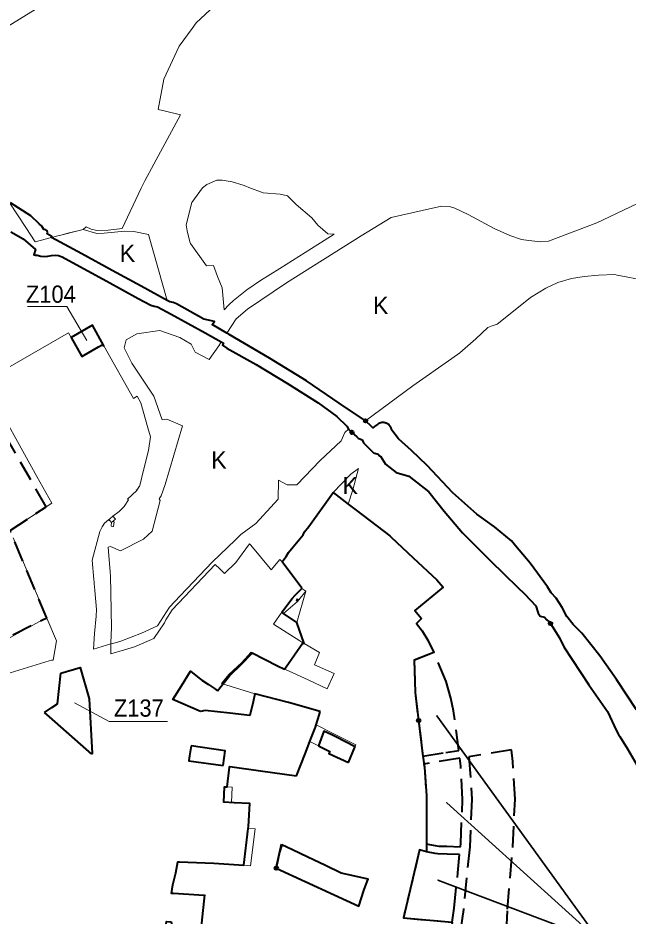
# Model space of a CAD drawing. Extents: x -650276 to -642489, y -1074425 to -1066658.
# Drawn here: x -646064 to -645214, y -1069855 to -1068604 of the extents above; entities that cross this region are included whole.
import ezdxf

# ---------------------------------------------------------------- set-up
doc = ezdxf.new("R2010")
doc.units = 0
doc.header["$LTSCALE"] = 9.6
doc.header["$PDMODE"] = 32
doc.header["$PDSIZE"] = 4.8
doc.linetypes.add('MEDIUM_DASHED', pattern=[4.5, 3, -1.5])
for name, color, linetype, lineweight in [('1', 7, 'Continuous', 13), ('4', 7, 'Continuous', 40), ('43', 7, 'Continuous', 13), ('44', 7, 'Continuous', 40), ('45', 7, 'Continuous', 40), ('46', 7, 'Continuous', 13), ('47', 7, 'Continuous', 13), ('61', 7, 'MEDIUM_DASHED', 40), ('62', 7, 'Continuous', 35)]:
    doc.layers.add(name, color=color, linetype=linetype, lineweight=lineweight)

msp = doc.modelspace()

# ---------------------------------------------------------------- hatches: boundary and pattern name
at = {"layer": '1'}
msp.add_hatch(color=256, dxfattribs=at).paths.add_polyline_path([(-645674.85, -1069417.32), (-645673.11, -1069414.76), (-645675.17, -1069413.36), (-645676.9, -1069415.91)])

# ---------------------------------------------------------------- linework, layer by layer
for p, q in [((-645673.11, -1069414.76), (-645663.41, -1069402.83)), ((-645694.21, -1069433.78), (-645674.85, -1069417.32))]:
    msp.add_line(p, q, dxfattribs=at)
for points in [[(-645954.63, -1068900.16), (-645938.5, -1068899.61), (-645919.15, -1068897.29), (-645892.53, -1068841.03), (-645887.72, -1068830.87), (-645875.187, -1068807.797), (-645837.77, -1068738.91), (-645858.824, -1068734.053), (-645868.98, -1068731.71), (-645860.91, -1068689.17), (-645839.55, -1068643.47), (-645821.454, -1068618.506), (-645816.02, -1068611.01), (-645751.23, -1068549.94)], [(-646028.19, -1068584.65), (-646136.66, -1068651.17), (-646149.99, -1068658.12), (-646149.04, -1068659.6), (-646152.41, -1068662.01), (-646157.02, -1068665.31), (-646115.89, -1068732.3), (-646110.72, -1068746.41), (-646100.168, -1068766.374), (-646094.58, -1068779.42), (-646089.04, -1068787.68), (-646088.06, -1068789.6), (-646105.32, -1068795.84), (-646115.95, -1068799.69), (-646109.35, -1068810.23), (-646081.72, -1068852.51), (-646075.56, -1068861.95), (-646053.3, -1068896.01)], [(-645766.07, -1068832.57), (-645779.72, -1068830.06), (-645787.33, -1068829.85), (-645801.24, -1068836.04), (-645807.42, -1068840.55), (-645822.26, -1068861.1), (-645829.76, -1068892.24), (-645828.71, -1068900.71), (-645825.84, -1068912.22), (-645824.55, -1068917.37), (-645823.83, -1068918.35), (-645801.57, -1068949.19), (-645791.76, -1068948.85), (-645786.17, -1068964.41), (-645779.83, -1068979.98), (-645777.16, -1069010.72)], [(-645777.16, -1069010.72), (-645770.47, -1069003.97), (-645764.17, -1068997.62), (-645745.65, -1068982.8), (-645726.46, -1068970.04), (-645699.5, -1068953.13), (-645637.82, -1068914.25), (-645623.92, -1068905.45), (-645632.76, -1068904.96), (-645646.49, -1068892.56), (-645655, -1068882.59), (-645676.5, -1068864.08), (-645688.54, -1068852.06), (-645699.05, -1068849.57), (-645722.69, -1068847.93), (-645742.6, -1068840.05), (-645746.62, -1068838.62), (-645750.71, -1068837.16), (-645766.07, -1068832.57)], [(-646053.3, -1068896.01), (-646040.33, -1068915.86), (-646017.55, -1068909.75), (-646010.48, -1068907.86), (-646004.88, -1068906.5), (-645980.93, -1068900.85), (-645973.36, -1068898.93), (-645969.47, -1068895.19), (-645962.49, -1068898.49), (-645954.63, -1068900.16)], [(-645739.3, -1069487.81), (-645702.82, -1069506.64), (-645659.84, -1069526.46), (-645633.29, -1069538.7), (-645623.545, -1069517.563), (-645651.26, -1069505.47), (-645644.18, -1069488.17), (-645665.58, -1069475.61), (-645667.31, -1069474.6), (-645671.75, -1069471.99), (-645708.48, -1069448.63), (-645696.45, -1069432.21), (-645682.28, -1069412.88), (-645678.06, -1069408.54), (-645668.61, -1069398.9), (-645696.19, -1069362.01), (-645699.25, -1069358.42), (-645711.75, -1069372.87), (-645713.14, -1069371.2), (-645740.01, -1069338.86), (-645741.7, -1069337.03), (-645760.59, -1069362.92), (-645776.73, -1069378.22), (-645783.23, -1069371.55), (-645789.7, -1069365.42), (-645849.68, -1069428.67), (-645858.11, -1069442.69), (-645860.14, -1069446.69), (-645875.02, -1069468.52), (-645902.19, -1069480.13), (-645916.13, -1069484.55), (-645934.97, -1069490.31), (-645935, -1069485.04), (-645935.03, -1069480.02), (-645935.05, -1069476.32), (-645959.32, -1069483.43), (-645957.52, -1069461.75), (-645955.52, -1069437.7), (-645954.74, -1069428.36), (-645957.17, -1069401.86), (-645957.69, -1069396.19), (-645958.02, -1069392.6), (-645958.23, -1069390.23), (-645958.59, -1069386.32), (-645961.03, -1069359.69), (-645950.49, -1069319.46), (-645947.21, -1069313.26), (-645943.67, -1069307.84), (-645938.32, -1069303.37), (-645936.46, -1069301.94), (-645932.07, -1069298.43), (-645923.56, -1069291.6), (-645916.39, -1069284.67), (-645910.4, -1069275.66), (-645911.64, -1069274.48), (-645898.96, -1069262.45), (-645899.61, -1069262.14), (-645899.34, -1069261.66), (-645898.67, -1069262.02), (-645895.95, -1069257.98), (-645895.9, -1069256.91), (-645895.36, -1069256.81), (-645895.25, -1069257.41), (-645888.98, -1069232.44), (-645882.56, -1069206.54), (-645879.84, -1069187.64), (-645883.39, -1069175.24), (-645893.36, -1069140.52), (-645898.3, -1069130.96), (-645903.35, -1069134.27), (-645944.69, -1069060.7), (-645946.84, -1069059.58), (-645952.21, -1069062.4), (-645975.48, -1069075.71), (-645990.13, -1069049.3), (-645993.85, -1069042.59), (-646106.31, -1069107.25)], [(-646107, -1069119.41), (-646037.99, -1069242.88), (-646017.15, -1069280.19), (-646075.49, -1069318.19)], [(-645928.65, -1069302.49), (-645932.07, -1069298.43), (-645936.46, -1069301.94), (-645938.32, -1069303.37)], [(-645938.32, -1069303.37), (-645935.71, -1069304.85), (-645934.38, -1069306.59)], [(-645934.38, -1069306.59), (-645934.21, -1069306.82), (-645934.66, -1069312.34), (-645934.17, -1069312.41), (-645931.98, -1069312.69), (-645931.24, -1069312.79), (-645930.48, -1069306.22), (-645931.2, -1069306.14), (-645931.07, -1069305.08), (-645933.12, -1069305.94), (-645928.65, -1069302.49)], [(-646071.21, -1069328.33), (-646023.96, -1069440.34), (-646010.65, -1069471.91), (-646015.16, -1069498.74), (-646017.63, -1069499.08), (-646020.75, -1069500), (-646075.48, -1069516.38)], [(-645668.61, -1069398.9), (-645678.06, -1069408.54), (-645682.28, -1069412.88), (-645696.45, -1069432.21), (-645694.21, -1069433.78)], [(-645676.9, -1069415.91), (-645675.17, -1069413.36), (-645673.11, -1069414.76), (-645663.41, -1069402.83), (-645668.61, -1069398.9)], [(-645694.21, -1069433.78), (-645674.85, -1069417.32), (-645676.9, -1069415.91)], [(-645696.45, -1069432.21), (-645708.48, -1069448.63), (-645671.75, -1069471.99)], [(-645665.58, -1069475.61), (-645675.91, -1069446.56), (-645694.21, -1069433.78), (-645696.45, -1069432.21)], [(-645671.75, -1069471.99), (-645667.31, -1069474.6), (-645665.58, -1069475.61)], [(-645808.28, -1069865.39), (-645806.07, -1069844.09), (-645804.38, -1069830.61), (-645804.28, -1069826.76), (-645812.18, -1069826.3), (-645847.62, -1069824.26), (-645850.63, -1069824.09), (-645848.35, -1069812.09), (-645844.57, -1069795.07), (-645841.41, -1069779.76), (-645791.2, -1069781.92), (-645749.48, -1069784.61), (-645740.394, -1069785.402), (-645733.972, -1069734.1), (-645743.36, -1069733.7), (-645743.01, -1069730.72), (-645741.43, -1069698.68), (-645766.701, -1069697.419), (-645766.017, -1069675.979), (-645773.02, -1069675.47), (-645769.36, -1069648), (-645769.298, -1069647.215), (-645726.57, -1069653.22), (-645676.34, -1069660.28), (-645670.23, -1069644.67), (-645664.19, -1069629.24), (-645657.52, -1069612.2), (-645629.78, -1069626.03), (-645630.93, -1069628.84), (-645603.7, -1069641.75), (-645594.58, -1069619.56), (-645593.609, -1069617.075), (-645625.81, -1069600.63), (-645648.68, -1069589.06), (-645644.56, -1069575.61), (-645643.16, -1069570.6), (-645734.5, -1069545.89), (-645780.85, -1069531.55), (-645770.66, -1069519.07), (-645753.05, -1069502.47), (-645739.3, -1069487.81)]]:
    msp.add_lwpolyline(points, dxfattribs=at)
for points in [[(-645675.91, -1069446.56), (-645663.41, -1069402.83), (-645673.11, -1069414.76), (-645674.85, -1069417.32), (-645694.21, -1069433.78)], [(-645674.85, -1069417.32), (-645673.11, -1069414.76), (-645675.17, -1069413.36), (-645676.9, -1069415.91)], [(-645647.25, -1069815.13), (-645623.75, -1069825.97), (-645589.23, -1069841.89), (-645582.31, -1069820.05), (-645577.52, -1069807.26), (-645576.34, -1069804.13), (-645613.84, -1069795.78), (-645635.79, -1069785.23), (-645660.57, -1069773.31), (-645681.76, -1069763.13), (-645698.16, -1069755.25), (-645705.3, -1069788.35)]]:
    msp.add_lwpolyline(points, close=True, dxfattribs=at)
at = {"layer": '4'}
for points in [[(-646027.49, -1069571.79), (-646017.39, -1069564.94), (-646009.52, -1069559.6), (-646004.7, -1069517.16)], [(-646004.7, -1069517.16), (-645977.73, -1069509.11), (-645965.36, -1069552.99), (-645960.78, -1069628.91), (-645961.36, -1069630.05)], [(-645961.36, -1069630.05), (-646020.4, -1069578.04), (-646027.49, -1069571.79)]]:
    msp.add_lwpolyline(points, dxfattribs=at)
at = {"layer": '4', "lineweight": 13}
msp.add_lwpolyline([(-645856.191, -1069584.407), (-645937.111, -1069584.407), (-645985.786, -1069558.403)], dxfattribs=at)
at = {"layer": '44'}
for points in [[(-645579.94, -1069165.52), (-645616.63, -1069140.8), (-645662.44, -1069109.89), (-645713.61, -1069078.06), (-645770.04, -1069045.34), (-645773.38, -1069043.46), (-645793.638, -1069031.021), (-645790.53, -1069027.19), (-645805.16, -1069023.52), (-645843.56, -1069002.41), (-645848.18, -1069000.48), (-645852.91, -1068999.62), (-645856.26, -1068997.79), (-645892.77, -1068977.86), (-645933.28, -1068955.74), (-645975.31, -1068932.8), (-646017.55, -1068909.75), (-646017.39, -1068908.42), (-646023.56, -1068905.05), (-646023.13, -1068903.12), (-646023.92, -1068900.73), (-646025.57, -1068899.39), (-646028.18, -1068898.89), (-646031.31, -1068894.32), (-646034.65, -1068891.12), (-646046.48, -1068879.92), (-646074.78, -1068861.51)], [(-646074.51, -1068901.9), (-646057.13, -1068911.62), (-646039.84, -1068926.67), (-646042.5, -1068933.91), (-646040.65, -1068934.59), (-646037.5, -1068934.7), (-646032.61, -1068936.1)], [(-646032.61, -1068936.1), (-646027.69, -1068936.6), (-646022.77, -1068936.12), (-646017.6, -1068934.89), (-646012.64, -1068934.34), (-646007.7, -1068935.18), (-646002.95, -1068936.95), (-645993.5, -1068942.1), (-645940.77, -1068970.74), (-645896.91, -1068994.75), (-645879.17, -1069004.02), (-645874.49, -1069005.73), (-645869.83, -1069006.45), (-645850.79, -1069016.84), (-645803.29, -1069042.92), (-645781.12, -1069055.29), (-645777.73, -1069057.2), (-645779.49, -1069059.92), (-645773.29, -1069063.99), (-645732.65, -1069086.82), (-645688.87, -1069113.44), (-645646.08, -1069140.37), (-645620.2, -1069159.26), (-645606.11, -1069172.98), (-645603.91, -1069176.86), (-645599, -1069181.48)], [(-645571.9, -1069173.43), (-645579.94, -1069165.52), (-645579.94, -1069165.52)], [(-645543.43, -1069178.39), (-645543.547, -1069177.727), (-645543.706, -1069177.053), (-645543.907, -1069176.37), (-645544.154, -1069175.682), (-645544.448, -1069174.993), (-645544.792, -1069174.308), (-645545.186, -1069173.63), (-645545.631, -1069172.966), (-645546.127, -1069172.32), (-645546.674, -1069171.699), (-645547.269, -1069171.107), (-645547.91, -1069170.551), (-645548.594, -1069170.034), (-645549.317, -1069169.563), (-645550.076, -1069169.141), (-645550.863, -1069168.772), (-645551.674, -1069168.459), (-645552.504, -1069168.203), (-645553.344, -1069168.007), (-645554.191, -1069167.87), (-645555.036, -1069167.793), (-645555.875, -1069167.772), (-645556.702, -1069167.808), (-645557.511, -1069167.896), (-645558.298, -1069168.035), (-645559.06, -1069168.219), (-645559.793, -1069168.445), (-645560.494, -1069168.709), (-645561.162, -1069169.007), (-645561.794, -1069169.334), (-645562.39, -1069169.686), (-645562.95, -1069170.06), (-645567.5, -1069173.46), (-645569.81, -1069175.03), (-645571.9, -1069173.43)], [(-645202.56, -1069568.23), (-645230.1, -1069525.98), (-645253.4, -1069493.06), (-645278.31, -1069461.33), (-645281.4, -1069458.4), (-645290.5, -1069449.03), (-645299.61, -1069437.97), (-645306.16, -1069425.55), (-645314.14, -1069412.54), (-645321.1, -1069405.21), (-645326.59, -1069396.64), (-645350.63, -1069363.98), (-645371.12, -1069339.47), (-645376.38, -1069332.65), (-645400.07, -1069313.32), (-645424.8, -1069295.24), (-645458.45, -1069265.56), (-645494.13, -1069227.63), (-645515.89, -1069206.66), (-645534.25, -1069190.56), (-645543.43, -1069178.39)], [(-645599, -1069181.48), (-645599, -1069181.48), (-645592.24, -1069187.73), (-645590.41, -1069189.45), (-645584.73, -1069191.88), (-645582.63, -1069195.88), (-645575.58, -1069203.57), (-645568.9, -1069209.87), (-645567.07, -1069210.45), (-645562.17, -1069212.02), (-645560.72, -1069214.25), (-645559.33, -1069214.54), (-645552.2, -1069225.59), (-645537.44, -1069237.41), (-645519.59, -1069242.38), (-645491.63, -1069264.25), (-645470.44, -1069291.24), (-645444.62, -1069321.35), (-645405.7, -1069360.27), (-645368.13, -1069397.37), (-645358.04, -1069406.84), (-645342.49, -1069423.06), (-645339.31, -1069433.27), (-645336.66, -1069437.47), (-645330.57, -1069438.89), (-645327.2, -1069442.53), (-645323.36, -1069445.79), (-645322.13, -1069447.96)], [(-645322.13, -1069447.96), (-645309.62, -1069467.79), (-645303.57, -1069480.49), (-645268.57, -1069533.23), (-645242.75, -1069570.26), (-645230.42, -1069597.39), (-645227.27, -1069602.68), (-645225.7, -1069605.32), (-645214.76, -1069622.37), (-645198.41, -1069650.49)]]:
    msp.add_lwpolyline(points, dxfattribs=at)
for p in [(-645579.94, -1069165.52), (-645599, -1069181.48), (-645322.13, -1069447.96)]:
    msp.add_point(p, dxfattribs=at)
at = {"layer": '45'}
msp.add_line((-645704.355, -1069788.786), (-645623.75, -1069825.97), dxfattribs=at)
for points in [[(-645944.69, -1069060.7), (-645960.67, -1069032.26), (-645990.13, -1069049.3), (-645975.48, -1069075.71), (-645952.21, -1069062.4)], [(-645944.69, -1069060.7), (-645960.67, -1069032.26), (-645990.13, -1069049.3), (-645975.48, -1069075.71), (-645952.21, -1069062.4)], [(-645952.21, -1069062.4), (-645946.84, -1069059.58), (-645944.69, -1069060.7)], [(-645952.21, -1069062.4), (-645946.84, -1069059.58), (-645944.69, -1069060.7)], [(-645668.722, -1069398.75), (-645696.19, -1069362.01), (-645692.38, -1069356.67), (-645690.81, -1069354.28), (-645687.22, -1069349), (-645680.8, -1069341.08), (-645667, -1069324.06), (-645664.89, -1069320.2), (-645658.9, -1069312.83), (-645625.11, -1069265.42), (-645604.114, -1069281.49), (-645594.94, -1069288.511)], [(-645594.94, -1069288.511), (-645583.13, -1069297.55), (-645546.19, -1069325.81), (-645544.26, -1069327.35), (-645513.41, -1069356.18), (-645480.72, -1069386.96), (-645471.738, -1069397.026), (-645511.464, -1069429.794), (-645501.878, -1069440.838)], [(-645675.91, -1069446.56), (-645694.21, -1069433.78), (-645696.45, -1069432.21), (-645682.28, -1069412.88), (-645678.06, -1069408.54), (-645668.61, -1069398.9), (-645668.722, -1069398.75)], [(-645501.878, -1069440.838), (-645508.994, -1069447.955), (-645501, -1069458), (-645493, -1069471), (-645484.783, -1069488.256), (-645512, -1069499), (-645511, -1069544), (-645506, -1069583)], [(-645786.388, -1069541.673), (-645779.376, -1069532.962), (-645778.754, -1069532.198), (-645769.369, -1069520.672), (-645768.995, -1069520.305), (-645752.715, -1069504.328), (-645738.986, -1069489.868), (-645737.897, -1069488.534), (-645702.82, -1069506.64), (-645692.87, -1069511.229), (-645690.84, -1069508.32), (-645667.31, -1069474.6), (-645665.58, -1069475.61), (-645675.91, -1069446.56)], [(-645836.44, -1069534.5), (-645824.05, -1069514.34), (-645811.75, -1069523.81), (-645808.1, -1069526.61), (-645799.07, -1069532.8), (-645790.62, -1069538.59), (-645786.388, -1069541.673)], [(-645810.08, -1069570.39), (-645848.78, -1069553.91), (-645836.44, -1069534.5)], [(-645643.16, -1069570.6), (-645687.29, -1069558.04), (-645734.5, -1069545.89), (-645736.8, -1069556.91), (-645741.14, -1069576.19), (-645769.04, -1069573), (-645803.513, -1069569.263), (-645810.08, -1069570.39)], [(-645676.34, -1069660.28), (-645670.23, -1069644.67), (-645664.19, -1069629.24), (-645657.52, -1069612.2), (-645656.15, -1069608.71), (-645649.91, -1069592.39), (-645648.68, -1069589.06), (-645644.56, -1069575.61), (-645643.16, -1069570.6)], [(-645506, -1069583), (-645500.137, -1069632.833), (-645500.137, -1069632.833)], [(-645594.58, -1069619.56), (-645621.56, -1069605.68), (-645626.95, -1069602.91), (-645638.203, -1069597.8), (-645645.715, -1069618.085)], [(-645645.715, -1069618.085), (-645629.78, -1069626.03), (-645630.93, -1069628.84), (-645603.7, -1069641.75)], [(-645823.082, -1069618.279), (-645823.13, -1069618.452), (-645825.295, -1069632.053), (-645826.133, -1069638.843), (-645826.151, -1069639.057), (-645778.45, -1069645.92)], [(-645823.082, -1069618.279), (-645823.13, -1069618.452), (-645825.295, -1069632.053), (-645826.133, -1069638.843), (-645826.151, -1069639.057), (-645778.45, -1069645.92)], [(-645778.45, -1069645.92), (-645775.46, -1069625.13), (-645823.082, -1069618.279)], [(-645778.45, -1069645.92), (-645775.46, -1069625.13), (-645823.082, -1069618.279)], [(-645603.7, -1069641.75), (-645594.818, -1069620.139), (-645594.58, -1069619.56)], [(-645500.137, -1069632.833), (-645498, -1069648), (-645495, -1069688), (-645495, -1069744), (-645495, -1069766), (-645504.976, -1069763.332), (-645527, -1069858), (-645459.312, -1069864.01), (-645464.288, -1069895.362), (-645465.756, -1069921.035), (-645469.701, -1069990.011)], [(-645839.721, -1069780.247), (-645839.658, -1069779.835), (-645791.2, -1069781.92), (-645749.48, -1069784.61), (-645743.36, -1069733.7), (-645743.01, -1069730.72), (-645741.43, -1069698.68), (-645763.24, -1069697.58), (-645777.62, -1069696.85), (-645776.45, -1069675.26), (-645773.02, -1069675.47), (-645769.36, -1069648), (-645769.264, -1069647.213), (-645726.57, -1069653.22), (-645676.34, -1069660.28)], [(-645696.517, -1069756.039), (-645700.028, -1069766.286), (-645704.355, -1069788.786)], [(-645660.57, -1069773.31), (-645681.76, -1069763.13), (-645696.517, -1069756.039)], [(-645804.185, -1069825.84), (-645804.28, -1069826.76), (-645812.18, -1069826.3), (-645847.62, -1069824.26), (-645850.63, -1069824.09), (-645848.35, -1069812.09), (-645844.57, -1069795.07), (-645841.41, -1069779.76), (-645839.658, -1069779.835), (-645839.721, -1069780.247)], [(-645613.84, -1069795.78), (-645635.79, -1069785.23), (-645652.378, -1069777.251), (-645660.57, -1069773.31)], [(-645623.75, -1069825.97), (-645589.23, -1069841.89), (-645582.31, -1069820.05), (-645577.52, -1069807.26), (-645576.34, -1069804.13), (-645578.134, -1069803.731), (-645613.84, -1069795.78)], [(-645742.967, -1069941.862), (-645768.424, -1069948.431), (-645833, -1069966), (-645880.431, -1069930.3), (-645874.219, -1069917.496), (-645869.262, -1069905.935), (-645863.95, -1069889.468), (-645857.289, -1069863.338), (-645857.204, -1069862.954), (-645850.92, -1069863.41), (-645849.79, -1069868.4), (-645808.84, -1069870.75), (-645808.28, -1069865.39), (-645804.185, -1069825.84)]]:
    msp.add_lwpolyline(points, dxfattribs=at)
for p in [(-645506, -1069583), (-645704.355, -1069788.786)]:
    msp.add_point(p, dxfattribs=at)
at = {"layer": '46'}
msp.add_lwpolyline([(-646051.21, -1069006.26), (-645996.286, -1069006.26), (-645968.211, -1069053.466)], dxfattribs=at)
msp.add_lwpolyline([(-646051.21, -1069006.26), (-645996.286, -1069006.26), (-645968.211, -1069053.466)], dxfattribs=at)
at = {"layer": '47'}
for points in [[(-645544.33, -1068882.17), (-645500.83, -1068872.25), (-645473.89, -1068866.13), (-645462.97, -1068866.88), (-645455.34, -1068868.9), (-645436.72, -1068877.85), (-645400.92, -1068897.18), (-645379.06, -1068907.27), (-645362.84, -1068912.83), (-645352.46, -1068914.25), (-645335.45, -1068915.77)], [(-645239.85, -1068880.94), (-645190.22, -1068857.23)], [(-645426.3, -1069051.02), (-645448.49, -1069070.45), (-645459.5, -1069078.59), (-645514.08, -1069116.5), (-645579.94, -1069165.52), (-645616.63, -1069140.8), (-645662.44, -1069109.89), (-645694.447, -1069089.98), (-645713.61, -1069078.06), (-645770.04, -1069045.34), (-645773.38, -1069043.46), (-645760.07, -1069023.11), (-645744.65, -1069009.71), (-645690.34, -1068973.16), (-645586.28, -1068907.71), (-645544.33, -1068882.17)], [(-645335.45, -1068915.77), (-645324.79, -1068914.82), (-645257.5, -1068889.68), (-645239.85, -1068880.94)], [(-645973.36, -1068898.93), (-645980.93, -1068900.85), (-645994.9, -1068904.1), (-646004.88, -1068906.5), (-646010.48, -1068907.86), (-646017.55, -1068909.75), (-645975.31, -1068932.8), (-645933.28, -1068955.74)], [(-645882.63, -1068905.88), (-645902.91, -1068901.43), (-645915.61, -1068901.02), (-645930.1, -1068902.47), (-645944.23, -1068904.13), (-645954.59, -1068904.41), (-645973.36, -1068898.93)], [(-645933.28, -1068955.74), (-645892.77, -1068977.86), (-645856.26, -1068997.79), (-645882.63, -1068905.88)], [(-645131.73, -1068995.69), (-645159.37, -1068981.11), (-645189.84, -1068969.91), (-645229.27, -1068962.28), (-645232.4, -1068961.67), (-645255.21, -1068962.49), (-645275.45, -1068964.38), (-645292.77, -1068966.91), (-645311.99, -1068972.74), (-645328.55, -1068980.37), (-645350.17, -1068993.33), (-645371.35, -1069010.64), (-645396.53, -1069030.88)], [(-645797.957, -1069080.052), (-645817.59, -1069069.6), (-645822.85, -1069058.8), (-645838.99, -1069049.31), (-645866.69, -1069039.37), (-645898.57, -1069044.24), (-645913.8, -1069052.51), (-645916.2, -1069063.8), (-645905.94, -1069085.11), (-645874.98, -1069131.01), (-645863.38, -1069163.79), (-645856.76, -1069163.17), (-645835.157, -1069172.184)], [(-645396.53, -1069030.88), (-645405.02, -1069033.34), (-645409.61, -1069035.17), (-645426.3, -1069051.02)], [(-645938.399, -1069347.452), (-645936.046, -1069375.651), (-645935.58, -1069381.24), (-645933.97, -1069453.52), (-645934.8, -1069474.71), (-645935.05, -1069476.32), (-645928.99, -1069474.55), (-645921.13, -1069472.25), (-645892.03, -1069461.43), (-645869.91, -1069451.02), (-645853.28, -1069425.27), (-645838.17, -1069409.28), (-645819.62, -1069389.66), (-645793.63, -1069362.15), (-645761.411, -1069331.17), (-645753.58, -1069323.64), (-645733.1, -1069308.58), (-645701.62, -1069274.36), (-645701.33, -1069247.86), (-645689, -1069254.5), (-645675.82, -1069254.48), (-645643.34, -1069220.59), (-645613.9, -1069193.45), (-645608.71, -1069181.51), (-645603.91, -1069176.86), (-645606.11, -1069172.98), (-645620.2, -1069159.26), (-645646.08, -1069140.37), (-645688.87, -1069113.44), (-645732.65, -1069086.82), (-645773.29, -1069063.99), (-645779.49, -1069059.92), (-645777.73, -1069057.2), (-645781.12, -1069055.29), (-645784.69, -1069060.74), (-645797.957, -1069080.052)], [(-645835.157, -1069172.184), (-645859.43, -1069254.08), (-645864.96, -1069269.78), (-645867.42, -1069274.21), (-645866.45, -1069276.32), (-645877.15, -1069319.06), (-645877.15, -1069319.06), (-645889.29, -1069330.52), (-645921.56, -1069346.6), (-645935.33, -1069340.64), (-645938.89, -1069341.56), (-645938.399, -1069347.452)], [(-645604.114, -1069281.49), (-645597.738, -1069261.522), (-645589.844, -1069231.908), (-645600.55, -1069239.93), (-645625.11, -1069265.42)], [(-645625.11, -1069265.42), (-645625.11, -1069265.42), (-645604.114, -1069281.49)], [(-646023.96, -1069440.34), (-646028.16, -1069441.58), (-646080.35, -1069469.89), (-646102.15, -1069479.49), (-646148.5, -1069503), (-646146.8, -1069506.6), (-646189.17, -1069528.74), (-646209.9, -1069538.5), (-646321.973, -1069686.855), (-646554.262, -1069762.602), (-646581.489, -1069759.421), (-646585.51, -1069769.57)], [(-646017.63, -1069499.08), (-646017.63, -1069499.08), (-646015.16, -1069498.74), (-646010.65, -1069471.91), (-646023.96, -1069440.34)], [(-646075.48, -1069516.38), (-646020.75, -1069500), (-646017.63, -1069499.08)]]:
    msp.add_lwpolyline(points, dxfattribs=at)
at = {"layer": '61'}
msp.add_lwpolyline([(-646583.457, -1069759.191), (-646554.262, -1069762.602), (-646321.973, -1069686.855), (-646209.9, -1069538.5), (-646146.8, -1069506.6), (-646148.5, -1069503), (-646028.16, -1069441.58), (-646023.96, -1069440.34), (-646075.49, -1069318.19), (-646025.14, -1069285.394), (-646153.307, -1069059.947)], dxfattribs=at)
for points in [[(-645506, -1069583), (-645500.137, -1069632.833), (-645468, -1069627.622), (-645450.05, -1069624.711), (-645457.223, -1069569.632), (-645461.32, -1069552.039), (-645467.477, -1069528.79), (-645484.783, -1069488.256), (-645512, -1069499), (-645511, -1069544)], [(-645374.642, -1069640.059), (-645376.605, -1069623.944), (-645435.877, -1069633.555), (-645431.642, -1069692.811), (-645434.826, -1069759.235), (-645443.679, -1069846.142), (-645449.445, -1069887.328), (-645455.84, -1069992.731), (-645379.881, -1070001.766), (-645385.95, -1069920.347), (-645382.14, -1069845.883), (-645378.587, -1069802.788), (-645374.542, -1069758.923), (-645371.563, -1069692.39)], [(-645495, -1069688), (-645495, -1069744), (-645495, -1069754.815), (-645491, -1069756), (-645478, -1069758), (-645466.517, -1069758.328), (-645447.852, -1069758.862), (-645447.398, -1069753.935), (-645444.664, -1069692.902), (-645447.387, -1069646.623), (-645448.725, -1069635.639), (-645498.61, -1069643.729), (-645498, -1069648)], [(-645504.976, -1069763.332), (-645527, -1069858), (-645464.93, -1069863.477), (-645459.312, -1069864.01), (-645456.586, -1069844.534), (-645451.227, -1069795.473), (-645448.864, -1069769.837), (-645466.353, -1069769.337), (-645478.997, -1069768.976), (-645482.753, -1069768.26), (-645495, -1069766)]]:
    msp.add_lwpolyline(points, close=True, dxfattribs=at)
at = {"layer": '62'}
msp.add_lwpolyline([(-645205.454, -1069890.903), (-645253.165, -1069890.903), (-645480.406, -1069576.285), (-645253.165, -1069890.903), (-645466.774, -1069697.69), (-645253.165, -1069890.903), (-645479.043, -1069805.455), (-645253.165, -1069890.903), (-645420.426, -1069951.415), (-645253.165, -1069890.903), (-645348.178, -1070139.662)], dxfattribs=at)

# ---------------------------------------------------------------- texts
at = {"layer": '4', "width": 0.95}
msp.add_text('Z137', height=24, dxfattribs=at).set_placement((-645930.722, -1069577.643))
at = {"layer": '43'}
for p in [(-645922.543, -1068943.866), (-645922.543, -1068943.866), (-645569.606, -1069016.557), (-645569.606, -1069016.557), (-645795.003, -1069231.861), (-645795.003, -1069231.861), (-645611.977, -1069267.447)]:
    msp.add_text('K', height=24, dxfattribs=at).set_placement(p)
at = {"layer": '46', "width": 0.95}
msp.add_text('Z104', height=24, dxfattribs=at).set_placement((-646053.286, -1069000.877))
msp.add_text('Z104', height=24, dxfattribs=at).set_placement((-646053.286, -1069000.877))

doc.saveas('drawing.dxf')
